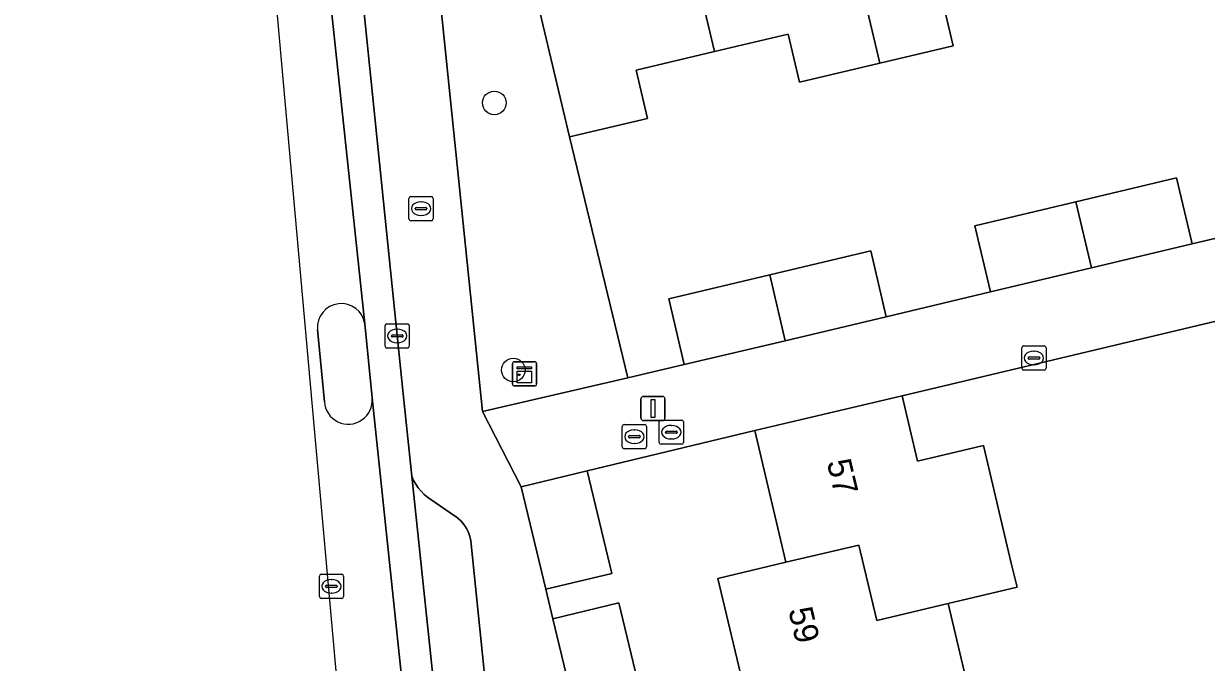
# Model space of a CAD drawing. Extents: x 158031 to 159244, y 380104 to 381214.
# Drawn here: x 158406.13 to 158455, y 380557.72 to 380584.14 of the extents above; entities that cross this region are included whole.
import ezdxf

# ---------------------------------------------------------------- set-up
doc = ezdxf.new("R2010")
doc.units = 0
for name, color, linetype in [('IMGEO_Boom', 7, 'Continuous'), ('IMGEO_Brandkraan', 7, 'Continuous'), ('IMGEO_Erf', 7, 'Continuous'), ('IMGEO_Groenvoorziening', 7, 'Continuous'), ('IMGEO_Hek', 7, 'Continuous'), ('IMGEO_Kast', 7, 'Continuous'), ('IMGEO_Kolk', 7, 'Continuous'), ('IMGEO_Lichtmast', 7, 'Continuous'), ('IMGEO_Muur', 7, 'Continuous'), ('IMGEO_Pand', 7, 'Continuous'), ('IMGEO_Pand_nummerreeks', 7, 'Continuous'), ('IMGEO_Parkeervlak_open', 7, 'Continuous'), ('IMGEO_Rijbaan_lokaal_gesloten', 7, 'Continuous'), ('IMGEO_Rioolput', 7, 'Continuous'), ('IMGEO_Verkeerseiland_gesloten', 7, 'Continuous'), ('IMGEO_Voetpad_open', 7, 'Continuous')]:
    doc.layers.add(name, color=color, linetype=linetype)

msp = doc.modelspace()

# ---------------------------------------------------------------- linework, layer by layer
at = {"layer": 'IMGEO_Boom'}
for centre in [(158425.578, 380580.859), (158426.362, 380569.811)]:
    msp.add_circle(centre, 0.489, dxfattribs=at)
at = {"layer": 'IMGEO_Brandkraan'}
for p, q in [((158422.05, 380576.06), (158422.05, 380576.912)), ((158422.125, 380576.986), (158422.977, 380576.986)), ((158422.352, 380576.529), (158422.75, 380576.529)), ((158422.538, 380576.766), (158422.563, 380576.766)), ((158423.051, 380576.912), (158423.051, 380576.06)), ((158422.309, 380576.48), (158422.309, 380576.492)), ((158422.747, 380576.443), (158422.349, 380576.443)), ((158422.561, 380576.206), (158422.536, 380576.206)), ((158422.793, 380576.492), (158422.793, 380576.48)), ((158422.977, 380575.986), (158422.125, 380575.986))]:
    msp.add_line(p, q, dxfattribs=at)
for points in [[(158422.05, 380576.06), (158422.05, 380576.912)], [(158422.125, 380576.986), (158422.977, 380576.986)], [(158423.051, 380576.912), (158423.051, 380576.06)], [(158422.977, 380575.986), (158422.125, 380575.986)]]:
    msp.add_lwpolyline(points, dxfattribs=at)
for centre, radius, start, end in [((158422.127, 380576.91), 0.0765, 91.552, 178.448), ((158422.127, 380576.91), 0.0765, 91.552, 178.448), ((158422.349, 380576.489), 0.0403, 85.8775, 175.7526), ((158422.754, 380576.491), 0.0386, 1.7309, 96.639), ((158422.975, 380576.91), 0.0765, 1.552, 88.448), ((158422.975, 380576.91), 0.0765, 1.552, 88.448), ((158422.127, 380576.062), 0.0765, 181.552, 268.448), ((158422.127, 380576.062), 0.0765, 181.552, 268.448), ((158422.346, 380576.479), 0.0366, 178.938, 274.7102), ((158422.75, 380576.486), 0.043, 264.8664, 352.4533), ((158422.975, 380576.062), 0.0765, 271.552, 358.448), ((158422.975, 380576.062), 0.0765, 271.552, 358.448)]:
    msp.add_arc(centre, radius, start, end, dxfattribs=at)
for centre, major_axis, ratio, start_param, end_param in [((158422.537, 380576.486), (-0.387, 0.002), 0.722429, 4.712389, 7.853982), ((158422.562, 380576.486), (-0.39, 0.002), 0.717154, 1.570796, 4.712389)]:
    msp.add_ellipse(centre, major_axis=major_axis, ratio=ratio, start_param=start_param, end_param=end_param, dxfattribs=at)
at = {"layer": 'IMGEO_Erf'}
for points in [[(158444.079, 380585.148), (158444.536, 380583.214), (158441.507, 380582.497), (158438.191, 380581.713), (158437.72, 380583.702), (158434.681, 380582.983), (158431.437, 380582.215), (158431.909, 380580.219), (158428.682, 380579.455), (158431.096, 380569.492), (158433.43, 380570.035), (158432.784, 380572.76), (158436.958, 380573.75), (158441.132, 380574.74), (158441.778, 380572.015), (158446.084, 380573.052), (158445.438, 380575.776), (158449.607, 380576.765), (158453.776, 380577.754), (158454.422, 380575.029), (158458.791, 380576.066)], [(158465.48, 380557.652), (158464.329, 380562.517), (158467.184, 380563.193), (158465.897, 380568.63), (158468.679, 380569.288), (158467.4, 380574.684), (158442.434, 380568.747), (158443.071, 380566.047), (158445.79, 380566.69), (158446.941, 380561.825), (158447.178, 380560.824), (158444.328, 380560.15), (158445.596, 380554.796)], [(158436.097, 380555.807), (158434.821, 380561.195), (158437.628, 380561.859), (158436.343, 380567.312), (158429.411, 380565.637), (158430.434, 380561.399), (158427.712, 380560.742), (158428.002, 380559.526), (158430.726, 380560.176), (158431.737, 380555.937)]]:
    msp.add_lwpolyline(points, dxfattribs=at)
at = {"layer": 'IMGEO_Groenvoorziening'}
msp.add_lwpolyline([(158424.178, 380598.251), (158422.041, 380597.744), (158425.085, 380568.092), (158431.096, 380569.492), (158428.682, 380579.455), (158426.877, 380587.082), (158425.116, 380594.369)], close=True, dxfattribs=at)
at = {"layer": 'IMGEO_Hek'}
for points in [[(158446.084, 380573.052), (158441.778, 380572.015)], [(158436.343, 380567.312), (158429.411, 380565.637)]]:
    msp.add_lwpolyline(points, dxfattribs=at)
at = {"layer": 'IMGEO_Kast'}
for p, q in [((158426.326, 380569.227), (158426.326, 380570.068)), ((158426.326, 380570.068), (158426.326, 380569.227)), ((158426.401, 380570.152), (158427.242, 380570.152)), ((158427.242, 380570.152), (158426.401, 380570.152)), ((158427.326, 380570.077), (158427.326, 380569.236)), ((158427.326, 380569.236), (158427.326, 380570.077)), ((158427.251, 380569.152), (158426.41, 380569.152)), ((158426.41, 380569.152), (158427.251, 380569.152))]:
    msp.add_line(p, q, dxfattribs=at)
for points in [[(158426.521, 380569.942), (158427.121, 380569.942), (158427.121, 380569.857), (158426.521, 380569.857), (158426.521, 380569.942)], [(158426.521, 380569.767), (158427.121, 380569.767), (158427.121, 380569.278), (158426.521, 380569.278), (158426.521, 380569.767)]]:
    msp.add_lwpolyline(points, dxfattribs=at)
msp.add_circle((158426.605, 380569.616), 0.0377, dxfattribs=at)
for centre, start, end in [((158426.404, 380570.074), 92.4484, 184.2845), ((158426.404, 380570.074), 92.4484, 184.2845), ((158427.248, 380570.074), 2.4484, 94.2845), ((158427.248, 380570.074), 2.4484, 94.2845), ((158426.404, 380569.23), 182.4484, 274.2845), ((158426.404, 380569.23), 182.4484, 274.2845), ((158427.248, 380569.23), 272.4484, 4.2845), ((158427.248, 380569.23), 272.4484, 4.2845)]:
    msp.add_arc(centre, 0.0779, start, end, dxfattribs=at)
at = {"layer": 'IMGEO_Kolk'}
for p, q in [((158421.064, 380570.796), (158421.064, 380571.648)), ((158421.139, 380571.722), (158421.991, 380571.722)), ((158422.065, 380571.648), (158422.065, 380570.796)), ((158421.323, 380571.216), (158421.323, 380571.228)), ((158421.761, 380571.179), (158421.363, 380571.179)), ((158421.366, 380571.265), (158421.764, 380571.265)), ((158421.552, 380571.502), (158421.577, 380571.502)), ((158421.807, 380571.228), (158421.807, 380571.216)), ((158421.991, 380570.722), (158421.139, 380570.722)), ((158421.575, 380570.942), (158421.55, 380570.942)), ((158447.376, 380569.882), (158447.376, 380570.734)), ((158447.451, 380570.808), (158448.303, 380570.808)), ((158448.377, 380570.734), (158448.377, 380569.882)), ((158447.635, 380570.302), (158447.635, 380570.314)), ((158448.073, 380570.265), (158447.675, 380570.265)), ((158447.678, 380570.351), (158448.076, 380570.351)), ((158447.864, 380570.588), (158447.889, 380570.588)), ((158448.119, 380570.314), (158448.119, 380570.302)), ((158448.303, 380569.808), (158447.451, 380569.808)), ((158447.887, 380570.028), (158447.862, 380570.028))]:
    msp.add_line(p, q, dxfattribs=at)
for points in [[(158421.064, 380570.796), (158421.064, 380571.648)], [(158421.139, 380571.722), (158421.991, 380571.722)], [(158422.065, 380571.648), (158422.065, 380570.796)], [(158421.991, 380570.722), (158421.139, 380570.722)], [(158447.376, 380569.882), (158447.376, 380570.734)], [(158447.451, 380570.808), (158448.303, 380570.808)], [(158448.377, 380570.734), (158448.377, 380569.882)], [(158448.303, 380569.808), (158447.451, 380569.808)]]:
    msp.add_lwpolyline(points, dxfattribs=at)
for centre, radius, start, end in [((158421.141, 380571.646), 0.0765, 91.552, 178.448), ((158421.141, 380571.646), 0.0765, 91.552, 178.448), ((158421.989, 380571.646), 0.0765, 1.552, 88.448), ((158421.989, 380571.646), 0.0765, 1.552, 88.448), ((158421.363, 380571.225), 0.0403, 85.8775, 175.7526), ((158421.36, 380571.215), 0.0366, 178.938, 274.7102), ((158421.764, 380571.222), 0.043, 264.8664, 352.4533), ((158421.768, 380571.227), 0.0386, 1.7309, 96.639), ((158421.141, 380570.798), 0.0765, 181.552, 268.448), ((158421.141, 380570.798), 0.0765, 181.552, 268.448), ((158421.989, 380570.798), 0.0765, 271.552, 358.448), ((158421.989, 380570.798), 0.0765, 271.552, 358.448), ((158447.453, 380570.732), 0.0765, 91.552, 178.448), ((158447.453, 380570.732), 0.0765, 91.552, 178.448), ((158448.301, 380570.732), 0.0765, 1.552, 88.448), ((158448.301, 380570.732), 0.0765, 1.552, 88.448), ((158447.675, 380570.311), 0.0403, 85.8775, 175.7526), ((158447.672, 380570.301), 0.0366, 178.938, 274.7102), ((158448.076, 380570.308), 0.043, 264.8664, 352.4533), ((158448.08, 380570.313), 0.0386, 1.7309, 96.639), ((158447.453, 380569.884), 0.0765, 181.552, 268.448), ((158447.453, 380569.884), 0.0765, 181.552, 268.448), ((158448.301, 380569.884), 0.0765, 271.552, 358.448), ((158448.301, 380569.884), 0.0765, 271.552, 358.448)]:
    msp.add_arc(centre, radius, start, end, dxfattribs=at)
for centre, major_axis, ratio, start_param, end_param in [((158421.551, 380571.222), (-0.387, 0.002), 0.722429, 4.712389, 7.853982), ((158421.576, 380571.222), (-0.39, 0.002), 0.717154, 1.570796, 4.712389), ((158447.863, 380570.308), (-0.387, 0.002), 0.722429, 4.712389, 7.853982), ((158447.888, 380570.308), (-0.39, 0.002), 0.717154, 1.570796, 4.712389)]:
    msp.add_ellipse(centre, major_axis=major_axis, ratio=ratio, start_param=start_param, end_param=end_param, dxfattribs=at)
at = {"layer": 'IMGEO_Lichtmast'}
for p, q in [((158431.738, 380568.721), (158432.528, 380568.721)), ((158432.528, 380568.721), (158431.738, 380568.721)), ((158431.638, 380567.821), (158431.638, 380568.621)), ((158431.638, 380568.621), (158431.638, 380567.821)), ((158432.628, 380568.621), (158432.628, 380567.821)), ((158432.628, 380567.821), (158432.628, 380568.621)), ((158432.528, 380567.721), (158431.738, 380567.721)), ((158431.738, 380567.721), (158432.528, 380567.721))]:
    msp.add_line(p, q, dxfattribs=at)
msp.add_lwpolyline([(158432.058, 380568.596), (158432.208, 380568.596), (158432.208, 380567.846), (158432.058, 380567.846), (158432.058, 380568.596)], dxfattribs=at)
for centre, start, end in [((158431.738, 380568.621), 90, 180), ((158431.738, 380568.621), 90, 180), ((158432.528, 380568.621), 0, 90), ((158432.528, 380568.621), 360, 90), ((158431.738, 380567.821), 180, 270), ((158431.738, 380567.821), 180, 270), ((158432.528, 380567.821), 270, 0), ((158432.528, 380567.821), 270, 0)]:
    msp.add_arc(centre, 0.1, start, end, dxfattribs=at)
at = {"layer": 'IMGEO_Muur'}
msp.add_lwpolyline([(158467.4, 380574.684), (158442.434, 380568.747)], dxfattribs=at)
at = {"layer": 'IMGEO_Pand'}
for points in [[(158439.701, 380590.128), (158441.507, 380582.497), (158444.536, 380583.214), (158444.079, 380585.148), (158447.406, 380585.935), (158445.579, 380593.649), (158442.524, 380592.926), (158443.001, 380590.909)], [(158439.701, 380590.128), (158437.385, 380589.58), (158436.9, 380591.628), (158432.859, 380590.672), (158434.681, 380582.983), (158437.72, 380583.702), (158438.191, 380581.713), (158441.507, 380582.497)], [(158432.859, 380590.672), (158428.905, 380589.736), (158429.392, 380587.677), (158426.877, 380587.082), (158428.682, 380579.455), (158431.909, 380580.219), (158431.437, 380582.215), (158434.681, 380582.983)], [(158450.253, 380574.041), (158454.422, 380575.029), (158453.776, 380577.754), (158449.607, 380576.765)], [(158450.253, 380574.041), (158449.607, 380576.765), (158445.438, 380575.776), (158446.084, 380573.052)], [(158437.604, 380571.025), (158441.778, 380572.015), (158441.132, 380574.74), (158436.958, 380573.75)], [(158437.604, 380571.025), (158436.958, 380573.75), (158432.784, 380572.76), (158433.43, 380570.035)], [(158437.628, 380561.859), (158440.645, 380562.574), (158441.383, 380559.454), (158444.328, 380560.15), (158447.178, 380560.824), (158446.941, 380561.825), (158445.79, 380566.69), (158443.071, 380566.047), (158442.434, 380568.747), (158436.343, 380567.312)], [(158427.712, 380560.742), (158430.434, 380561.399), (158429.411, 380565.637), (158426.69, 380564.977)], [(158437.628, 380561.859), (158434.821, 380561.195), (158436.097, 380555.807), (158439.033, 380556.503), (158439.764, 380553.416), (158442.702, 380554.111), (158445.596, 380554.796), (158444.328, 380560.15), (158441.383, 380559.454), (158440.645, 380562.574)], [(158429.013, 380555.287), (158431.737, 380555.937), (158430.726, 380560.176), (158428.002, 380559.526)]]:
    msp.add_lwpolyline(points, close=True, dxfattribs=at)
at = {"layer": 'IMGEO_Parkeervlak_open'}
msp.add_lwpolyline([(158429.151, 380518.329), (158428.941, 380520.326), (158424.623, 380562.606), (158424.608, 380562.741), (158424.582, 380562.874), (158424.544, 380563.004), (158424.494, 380563.13), (158424.433, 380563.252), (158424.361, 380563.367), (158424.28, 380563.476), (158424.189, 380563.576), (158424.09, 380563.669), (158423.982, 380563.752), (158423.972, 380563.759), (158422.916, 380564.479), (158422.822, 380564.547), (158422.682, 380564.665), (158422.552, 380564.795), (158422.435, 380564.936), (158422.33, 380565.088), (158422.24, 380565.248), (158422.164, 380565.415), (158427.489, 380514.895)], dxfattribs=at)
at = {"layer": 'IMGEO_Rijbaan_lokaal_gesloten'}
for points in [[(158413.789, 380649.734), (158409.858, 380670.847), (158409.491, 380672.368), (158408.127, 380672.053), (158406.127, 380671.591), (158409.043, 380659.289), (158410.456, 380653.327), (158415.505, 380596.808), (158424.244, 380498.985), (158407.741, 380473.826)], [(158420.225, 380571.721), (158414.351, 380627.022), (158412.561, 380645.899), (158413.784, 380645.974)], [(158418.556, 380568.5), (158418.276, 380571.487)], [(158428.101, 380507.396), (158428.042, 380509.13), (158427.879, 380510.852), (158427.809, 380511.591), (158426.535, 380511.584), (158420.529, 380568.655)]]:
    msp.add_lwpolyline(points, dxfattribs=at)
msp.add_lwpolyline([(158426.535, 380511.584), (158427.809, 380511.591), (158427.489, 380514.895), (158422.164, 380565.415), (158421.809, 380568.833), (158418.932, 380596.973), (158418.795, 380598.318), (158418.53, 380600.821), (158418.267, 380603.305), (158417.868, 380607.069), (158416.136, 380623.426), (158415.915, 380625.516), (158415.743, 380627.168), (158413.784, 380645.974), (158412.561, 380645.899), (158414.351, 380627.022), (158420.225, 380571.721), (158420.529, 380568.655)], close=True, dxfattribs=at)
for centre, radius, start, end in [((158419.253, 380571.579), 0.982, 8.3018, 185.3907), ((158419.544, 380568.561), 0.99, 183.5146, 5.4694)]:
    msp.add_arc(centre, radius, start, end, dxfattribs=at)
at = {"layer": 'IMGEO_Rioolput'}
for p, q in [((158432.468, 380567.74), (158433.32, 380567.74)), ((158430.866, 380566.629), (158430.866, 380567.481)), ((158430.941, 380567.555), (158431.793, 380567.555)), ((158431.354, 380567.335), (158431.379, 380567.335)), ((158431.867, 380567.481), (158431.867, 380566.629)), ((158432.393, 380566.814), (158432.393, 380567.666)), ((158432.652, 380567.234), (158432.652, 380567.246)), ((158432.695, 380567.283), (158433.093, 380567.283)), ((158432.881, 380567.52), (158432.906, 380567.52)), ((158433.136, 380567.246), (158433.136, 380567.234)), ((158433.394, 380567.666), (158433.394, 380566.814)), ((158431.125, 380567.049), (158431.125, 380567.061)), ((158431.563, 380567.012), (158431.165, 380567.012)), ((158431.168, 380567.098), (158431.566, 380567.098)), ((158431.377, 380566.775), (158431.352, 380566.775)), ((158431.609, 380567.061), (158431.609, 380567.049)), ((158433.32, 380566.74), (158432.468, 380566.74)), ((158433.09, 380567.197), (158432.692, 380567.197)), ((158432.904, 380566.96), (158432.879, 380566.96)), ((158431.793, 380566.555), (158430.941, 380566.555)), ((158418.422, 380561.364), (158419.274, 380561.364)), ((158418.347, 380560.438), (158418.347, 380561.29)), ((158418.649, 380560.907), (158419.047, 380560.907)), ((158418.835, 380561.144), (158418.86, 380561.144)), ((158419.348, 380561.29), (158419.348, 380560.438)), ((158418.606, 380560.858), (158418.606, 380560.87)), ((158419.044, 380560.821), (158418.646, 380560.821)), ((158418.858, 380560.584), (158418.833, 380560.584)), ((158419.09, 380560.87), (158419.09, 380560.858)), ((158419.274, 380560.364), (158418.422, 380560.364))]:
    msp.add_line(p, q, dxfattribs=at)
for points in [[(158432.468, 380567.74), (158433.32, 380567.74)], [(158430.866, 380566.629), (158430.866, 380567.481)], [(158430.941, 380567.555), (158431.793, 380567.555)], [(158431.867, 380567.481), (158431.867, 380566.629)], [(158432.393, 380566.814), (158432.393, 380567.666)], [(158433.394, 380567.666), (158433.394, 380566.814)], [(158433.32, 380566.74), (158432.468, 380566.74)], [(158431.793, 380566.555), (158430.941, 380566.555)], [(158418.422, 380561.364), (158419.274, 380561.364)], [(158418.347, 380560.438), (158418.347, 380561.29)], [(158419.348, 380561.29), (158419.348, 380560.438)], [(158419.274, 380560.364), (158418.422, 380560.364)]]:
    msp.add_lwpolyline(points, dxfattribs=at)
for centre, radius, start, end in [((158432.47, 380567.664), 0.0765, 91.552, 178.448), ((158432.47, 380567.664), 0.0765, 91.552, 178.448), ((158433.318, 380567.664), 0.0765, 1.552, 88.448), ((158433.318, 380567.664), 0.0765, 1.552, 88.448), ((158430.943, 380567.479), 0.0765, 91.552, 178.448), ((158430.943, 380567.479), 0.0765, 91.552, 178.448), ((158431.791, 380567.479), 0.0765, 1.552, 88.448), ((158431.791, 380567.479), 0.0765, 1.552, 88.448), ((158432.692, 380567.243), 0.0403, 85.8775, 175.7526), ((158432.689, 380567.233), 0.0366, 178.938, 274.7102), ((158433.093, 380567.24), 0.043, 264.8664, 352.4533), ((158433.097, 380567.245), 0.0386, 1.7309, 96.639), ((158431.165, 380567.058), 0.0403, 85.8775, 175.7526), ((158431.162, 380567.048), 0.0366, 178.938, 274.7102), ((158431.566, 380567.055), 0.043, 264.8664, 352.4533), ((158431.57, 380567.06), 0.0386, 1.7309, 96.639), ((158432.47, 380566.816), 0.0765, 181.552, 268.448), ((158432.47, 380566.816), 0.0765, 181.552, 268.448), ((158433.318, 380566.816), 0.0765, 271.552, 358.448), ((158433.318, 380566.816), 0.0765, 271.552, 358.448), ((158430.943, 380566.631), 0.0765, 181.552, 268.448), ((158430.943, 380566.631), 0.0765, 181.552, 268.448), ((158431.791, 380566.631), 0.0765, 271.552, 358.448), ((158431.791, 380566.631), 0.0765, 271.552, 358.448), ((158418.424, 380561.288), 0.0765, 91.552, 178.448), ((158418.424, 380561.288), 0.0765, 91.552, 178.448), ((158419.272, 380561.288), 0.0765, 1.552, 88.448), ((158419.272, 380561.288), 0.0765, 1.552, 88.448), ((158418.646, 380560.867), 0.0403, 85.8775, 175.7526), ((158419.051, 380560.869), 0.0386, 1.7309, 96.639), ((158418.424, 380560.44), 0.0765, 181.552, 268.448), ((158418.424, 380560.44), 0.0765, 181.552, 268.448), ((158418.643, 380560.857), 0.0366, 178.938, 274.7102), ((158419.047, 380560.864), 0.043, 264.8664, 352.4533), ((158419.272, 380560.44), 0.0765, 271.552, 358.448), ((158419.272, 380560.44), 0.0765, 271.552, 358.448)]:
    msp.add_arc(centre, radius, start, end, dxfattribs=at)
for centre, major_axis, ratio, start_param, end_param in [((158431.353, 380567.055), (-0.387, 0.002), 0.722429, 4.712389, 7.853982), ((158431.378, 380567.055), (-0.39, 0.002), 0.717154, 1.570796, 4.712389), ((158432.88, 380567.24), (-0.387, 0.002), 0.722429, 4.712389, 7.853982), ((158432.905, 380567.24), (-0.39, 0.002), 0.717154, 1.570796, 4.712389), ((158418.834, 380560.864), (-0.387, 0.002), 0.722429, 4.712389, 7.853982), ((158418.859, 380560.864), (-0.39, 0.002), 0.717154, 1.570796, 4.712389)]:
    msp.add_ellipse(centre, major_axis=major_axis, ratio=ratio, start_param=start_param, end_param=end_param, dxfattribs=at)
at = {"layer": 'IMGEO_Verkeerseiland_gesloten'}
for points in [[(158420.529, 380568.655), (158420.225, 380571.721)], [(158418.276, 380571.487), (158418.556, 380568.5)]]:
    msp.add_lwpolyline(points, dxfattribs=at)
for centre, radius, start, end in [((158419.253, 380571.579), 0.982, 8.3018, 185.3907), ((158419.544, 380568.561), 0.99, 183.5146, 5.4694)]:
    msp.add_arc(centre, radius, start, end, dxfattribs=at)
at = {"layer": 'IMGEO_Voetpad_open'}
for points in [[(158429.013, 380555.287), (158428.002, 380559.526), (158427.712, 380560.742), (158426.69, 380564.977), (158425.085, 380568.092), (158422.041, 380597.744)], [(158418.932, 380596.973), (158421.809, 380568.833), (158422.164, 380565.415), (158422.24, 380565.248), (158422.33, 380565.088), (158422.435, 380564.936), (158422.552, 380564.795), (158422.682, 380564.665), (158422.822, 380564.547), (158422.916, 380564.479), (158423.972, 380563.759), (158423.982, 380563.752), (158424.09, 380563.669), (158424.189, 380563.576), (158424.28, 380563.476), (158424.361, 380563.367), (158424.433, 380563.252), (158424.494, 380563.13), (158424.544, 380563.004), (158424.582, 380562.874), (158424.608, 380562.741), (158424.623, 380562.606), (158428.941, 380520.326)], [(158482.429, 380581.669), (158479.84, 380581.054), (158475.663, 380580.065), (158471.485, 380579.077), (158467.136, 380578.045), (158462.963, 380577.055), (158458.791, 380576.066), (158454.422, 380575.029), (158450.253, 380574.041), (158446.084, 380573.052), (158441.778, 380572.015), (158437.604, 380571.025), (158433.43, 380570.035), (158431.096, 380569.492), (158425.085, 380568.092), (158426.69, 380564.977), (158429.411, 380565.637), (158436.343, 380567.312), (158442.434, 380568.747), (158467.4, 380574.684), (158477.534, 380577.087), (158478.208, 380574.268), (158481.097, 380574.956)]]:
    msp.add_lwpolyline(points, dxfattribs=at)

# ---------------------------------------------------------------- texts
at = {"layer": 'IMGEO_Pand_nummerreeks'}
for s, rotation, p in [('57', 283.3224, (158439.313, 380566.009)), ('59', 283.3235, (158437.721, 380559.886))]:
    msp.add_text(s, height=1, rotation=rotation, dxfattribs=at).set_placement(p)

doc.saveas('drawing.dxf')
